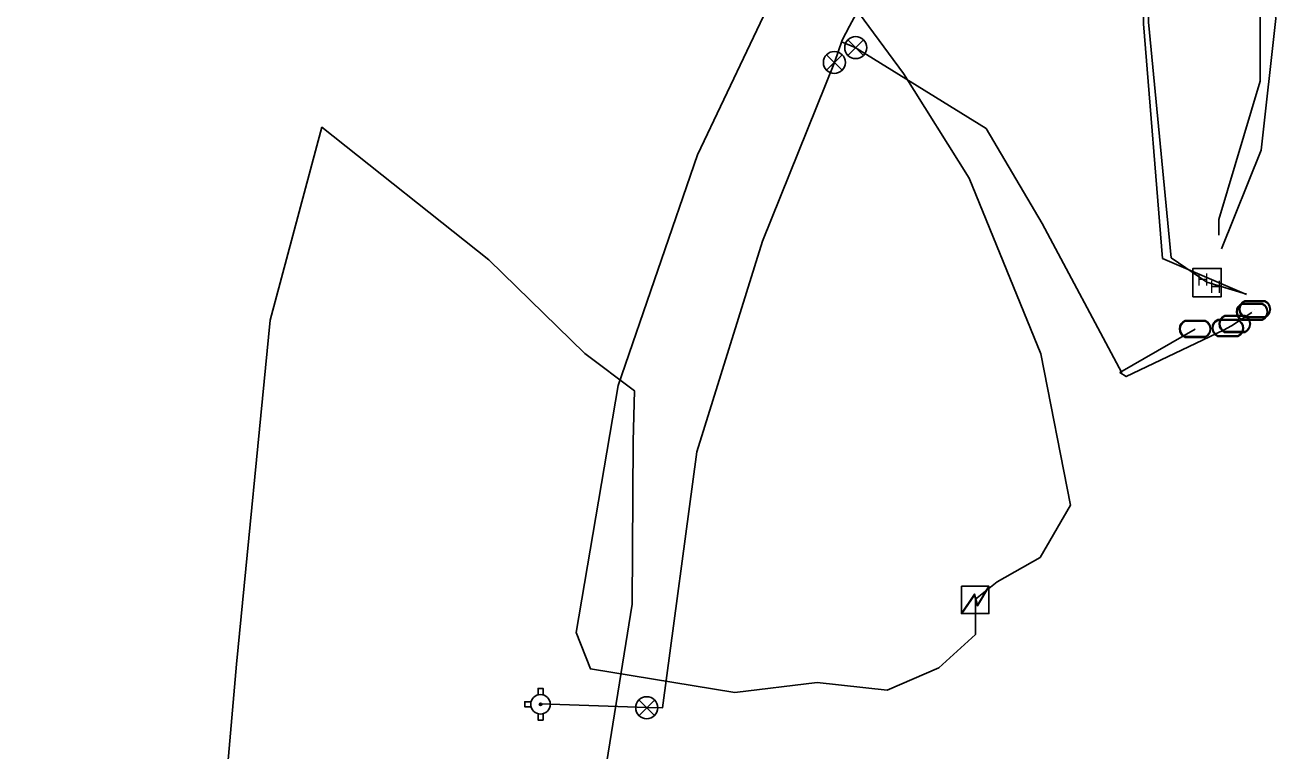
# Model space of a CAD drawing. Extents: x 2070721 to 2083039, y 729290 to 737883.
# Drawn here: x 2080544.7 to 2080798.5, y 734354.3 to 734501.5 of the extents above; entities that cross this region are included whole.
import ezdxf

# ---------------------------------------------------------------- set-up
doc = ezdxf.new("R2010")
doc.units = 0
for name, color, linetype in [('COGO Default Point Elevation', 7, 'Continuous'), ('COGO Default Point Number', 7, 'Continuous'), ('Exist Utilities Telephone UG Cable Cogo Point CELL', 7, 'Continuous'), ('Exist Utilities Telephone UG Cable SUE LOS C Cogo Number', 7, 'Continuous'), ('Exist Utilities Telephone UG FO Cogo Point CELL', 7, 'Continuous'), ('Exist Utilities TV Pedestal CELL', 7, 'Continuous'), ('Exist Utilities TV Pedestal Cogo Elevation', 7, 'Continuous'), ('Exist Utilities TV UG Cable Cogo Point CELL', 7, 'Continuous'), ('Exist Utilities TV UG Cable SUE LOS C Cogo Comment', 7, 'Continuous'), ('Exist Utilities TV UG Cable SUE LOS C Cogo Point CELL', 7, 'Continuous'), ('Exist Utilities Water UG Line SUE LOS B Cogo Number', 7, 'Continuous')]:
    doc.layers.add(name, color=color, linetype=linetype)

msp = doc.modelspace()

# ---------------------------------------------------------------- linework, layer by layer
at = {"layer": 'COGO Default Point Elevation'}
for points in [[(2080714.8, 734498.46), (2080711.65, 734495.31), (2080713.22, 734496.89), (2080714.8, 734495.31), (2080711.65, 734498.46)], [(2080710.47, 734495.45), (2080707.32, 734492.3), (2080708.9, 734493.87), (2080710.47, 734492.3), (2080707.32, 734495.45)], [(2080672.43, 734364.65), (2080669.28, 734361.5), (2080670.85, 734363.08), (2080672.43, 734361.5), (2080669.28, 734364.65)]]:
    msp.add_lwpolyline(points, dxfattribs=at)
for centre in [(2080713.22, 734496.89), (2080708.9, 734493.87), (2080670.85, 734363.08)]:
    msp.add_circle(centre, 2.23, dxfattribs=at)
at = {"layer": 'COGO Default Point Number'}
msp.add_line((2080649.3, 734363.79), (2080649.3, 734363.79), dxfattribs=at)
for points in [[(2080648.79, 734365.7), (2080648.79, 734366.99), (2080649.82, 734366.99), (2080649.82, 734365.68)], [(2080647.39, 734364.3), (2080646.1, 734364.3), (2080646.1, 734363.28), (2080647.39, 734363.28)], [(2080648.79, 734361.88), (2080648.79, 734360.59), (2080649.82, 734360.59), (2080649.82, 734361.9)]]:
    msp.add_lwpolyline(points, dxfattribs=at)
for radius in [1.98, 0.243]:
    msp.add_circle((2080649.3, 734363.79), radius, dxfattribs=at)
at = {"layer": 'Exist Utilities Telephone UG Cable Cogo Point CELL'}
msp.add_line((2080784.5, 734449.27), (2080784.5, 734449.27), dxfattribs=at)
msp.add_lwpolyline([(2080781.63, 734446.39), (2080787.38, 734446.39), (2080787.38, 734452.14), (2080781.63, 734452.14), (2080781.63, 734446.39)], dxfattribs=at)
at = {"layer": 'Exist Utilities Telephone UG Cable SUE LOS C Cogo Number'}
msp.add_line((2080737.52, 734385.1), (2080737.52, 734385.1), dxfattribs=at)
msp.add_lwpolyline([(2080734.68, 734387.71), (2080740.23, 734387.71), (2080740.23, 734382.16), (2080734.68, 734382.16)], close=True, dxfattribs=at)
for points in [[(2080734.68, 734382.16), (2080737.32, 734386.11), (2080737.95, 734383.9), (2080740.23, 734387.71)], [(2080734.75, 734382.16), (2080737.32, 734385.9), (2080737.91, 734383.71), (2080740.23, 734387.56)]]:
    msp.add_lwpolyline(points, dxfattribs=at)
at = {"layer": 'Exist Utilities Telephone UG FO Cogo Point CELL'}
for p, q in [((2080793.61, 734443.32), (2080793.61, 734443.32)), ((2080794.18, 734443.88), (2080794.18, 734443.88)), ((2080788.71, 734440.05), (2080788.71, 734440.05)), ((2080790.11, 734440.87), (2080790.11, 734440.87)), ((2080782.06, 734439.86), (2080782.06, 734439.86))]:
    msp.add_line(p, q, dxfattribs=at)
for points in [[(2080792.14, 734445.58), (2080796.22, 734445.58)], [(2080792.14, 734445.44), (2080796.22, 734445.44)], [(2080788.08, 734442.57), (2080792.15, 734442.57)], [(2080791.57, 734445.02), (2080795.65, 734445.02)], [(2080791.57, 734444.88), (2080795.65, 734444.88)], [(2080780.02, 734441.56), (2080784.1, 734441.56)], [(2080780.02, 734441.43), (2080784.1, 734441.43)], [(2080786.67, 734441.75), (2080790.75, 734441.75)], [(2080786.67, 734441.61), (2080790.75, 734441.61)], [(2080788.08, 734442.43), (2080792.15, 734442.43)], [(2080795.65, 734441.76), (2080791.55, 734441.76)], [(2080795.65, 734441.62), (2080791.55, 734441.62)], [(2080796.22, 734442.31), (2080792.12, 734442.31)], [(2080796.22, 734442.18), (2080792.12, 734442.18)], [(2080784.1, 734438.3), (2080780, 734438.3)], [(2080784.1, 734438.16), (2080780, 734438.16)], [(2080790.75, 734438.49), (2080786.65, 734438.49)], [(2080790.75, 734438.35), (2080786.65, 734438.35)], [(2080792.15, 734439.31), (2080788.05, 734439.31)], [(2080792.15, 734439.17), (2080788.05, 734439.17)]]:
    msp.add_lwpolyline(points, dxfattribs=at)
for centre, radius, start, end in [((2080792.87, 734443.87), 1.86, 113.178, 245.9794), ((2080792.89, 734443.87), 1.73, 115.3009, 243.7824), ((2080795.47, 734443.88), 1.86, 293.6483, 66.3084), ((2080795.49, 734443.88), 1.73, 295.1272, 64.8728), ((2080788.81, 734440.87), 1.86, 113.178, 245.9794), ((2080792.3, 734443.31), 1.86, 113.178, 245.9794), ((2080792.31, 734443.31), 1.73, 115.3009, 243.7824), ((2080791.41, 734440.87), 1.86, 293.6483, 66.3084), ((2080794.9, 734443.32), 1.86, 293.6483, 66.3084), ((2080794.92, 734443.32), 1.73, 295.1272, 64.8728), ((2080780.75, 734439.86), 1.86, 113.178, 245.9794), ((2080780.76, 734439.86), 1.73, 115.3009, 243.7824), ((2080783.35, 734439.87), 1.86, 293.6483, 66.3084), ((2080783.37, 734439.86), 1.73, 295.1272, 64.8728), ((2080787.4, 734440.05), 1.86, 113.178, 245.9794), ((2080787.41, 734440.04), 1.73, 115.3009, 243.7824), ((2080788.82, 734440.87), 1.73, 115.3009, 243.7824), ((2080790, 734440.05), 1.86, 293.6483, 66.3084), ((2080790.01, 734440.05), 1.73, 295.1272, 64.8728), ((2080791.42, 734440.87), 1.73, 295.1272, 64.8728)]:
    msp.add_arc(centre, radius, start, end, dxfattribs=at)
at = {"layer": 'Exist Utilities TV Pedestal CELL'}
msp.add_lwpolyline([(2080792.49, 734446.91), (2080784.46, 734449.31), (2080777.2, 734454.29), (2080772.59, 734502.03), (2080772.98, 734523.68), (2080773.64, 734539.98), (2080772.68, 734584.01), (2080781.47, 734612.06)], dxfattribs=at)
at = {"layer": 'Exist Utilities TV Pedestal Cogo Elevation'}
for points in [[(2080710.45, 734498.38), (2080711.94, 734501.21), (2080726.31, 734527.8)], [(2080649.3, 734363.85), (2080670.85, 734363.12), (2080674.01, 734363.05), (2080681.01, 734414.95), (2080694.32, 734457.66), (2080708.93, 734493.88), (2080710.45, 734498.38)], [(2080767.17, 734430.94), (2080751.03, 734461.24), (2080739.67, 734480.49), (2080713.13, 734496.9), (2080710.35, 734498.08)], [(2080793.57, 734443.18), (2080789.45, 734440.5), (2080787.79, 734439.62), (2080768.11, 734430.22), (2080766.81, 734431.01), (2080782.06, 734439.79)]]:
    msp.add_lwpolyline(points, dxfattribs=at)
at = {"layer": 'Exist Utilities TV UG Cable Cogo Point CELL'}
msp.add_lwpolyline([(2080392.43, 734459.45), (2080392.18, 734455.98), (2080369.79, 734491.21), (2080371.64, 734506.16), (2080398.8, 734522.93), (2080423.1, 734536.76), (2080488.87, 734560.43), (2080551.19, 734581.93), (2080605.97, 734600.8), (2080683.17, 734629.37), (2080713.38, 734633.09), (2080745.42, 734609.78), (2080760.77, 734576.63), (2080781.91, 734561.06), (2080789.84, 734547.84), (2080795.45, 734523.96), (2080798.47, 734502.81), (2080795.45, 734476.11), (2080787.39, 734456.13)], dxfattribs=at)
at = {"layer": 'Exist Utilities TV UG Cable SUE LOS C Cogo Comment'}
for points in [[(2080667.78, 734563.47), (2080675.67, 734558.83), (2080693.85, 734531.06), (2080722.9, 734491.66), (2080736.23, 734470.41), (2080750.76, 734434.85), (2080756.8, 734404.17), (2080750.61, 734393.55), (2080741.92, 734388.6), (2080737.52, 734385.1)], [(2080697.31, 734510.51), (2080697.15, 734508.83), (2080681.13, 734475.16), (2080665.04, 734428.4), (2080656.55, 734378.37), (2080659.43, 734370.95), (2080688.68, 734366.16), (2080705.41, 734368.17), (2080719.63, 734366.67), (2080730.12, 734371.17), (2080737.52, 734377.9), (2080737.52, 734385.1)], [(2080660.22, 734254.22), (2080665.36, 734271.75), (2080659.75, 734333.73), (2080667.87, 734384.1), (2080668.08, 734417.09), (2080668.36, 734427.32), (2080658.31, 734434.88), (2080638.79, 734453.87), (2080604.95, 734480.75), (2080594.48, 734441.62), (2080587.63, 734371.92), (2080583.9, 734329.12), (2080584.82, 734300.58), (2080593.77, 734266.89), (2080602.76, 734233.65), (2080617.91, 734184.32)]]:
    msp.add_lwpolyline(points, dxfattribs=at)
at = {"layer": 'Exist Utilities TV UG Cable SUE LOS C Cogo Point CELL'}
msp.add_lwpolyline([(2080792.52, 734446.86), (2080775.46, 734454.16), (2080771.57, 734501.71), (2080771.41, 734523.8), (2080772.11, 734540.7), (2080770.17, 734557.91), (2080769.35, 734590.18), (2080775.5, 734606.58), (2080780.96, 734613.32)], dxfattribs=at)
at = {"layer": 'Exist Utilities Water UG Line SUE LOS B Cogo Number'}
msp.add_lwpolyline([(2080652.77, 734625.25), (2080667.42, 734617.06), (2080717.34, 734601.19), (2080782.55, 734556.25), (2080795.25, 734516.63), (2080795.25, 734490.1), (2080786.86, 734462.06), (2080786.86, 734458.84)], dxfattribs=at)

# ---------------------------------------------------------------- texts
at = {"layer": 'Exist Utilities Telephone UG Cable Cogo Point CELL'}
for p in [(2080782.42, 734448.62), (2080784.99, 734447.16)]:
    msp.add_text('H', height=2.5, dxfattribs=at).set_placement(p)

doc.saveas('drawing.dxf')
